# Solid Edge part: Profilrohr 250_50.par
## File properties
Username: ahadarics
Dokumentum tartalom típus: 0
Author: ahadarics
Last saved by: ahadarics
Revision: 79
Sűrűség: 0,000 kg/m^3
Pontosság: 0,990
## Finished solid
Body 1: solid body, 8 faces, 12 edges, 6 vertices.
  Faces by surface: cone 4, cylinder 2, plane 2
  Edges by curve: circle 8, line 4
Bounding box of the edges (mm): 262.000 x 130.000 x 262.000, from (-131, -77.5, -131) to (131, 52.5, 131).
Cylindrical faces by radius (mm): R125 x1, R131 x1
Conical faces (half-angle, radius in mm at the cone's reference point): 45 deg R125.25 x2, 45 deg R130.9 x2
Planar faces by outward normal: +y 1, -y 1
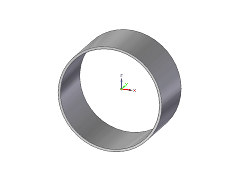
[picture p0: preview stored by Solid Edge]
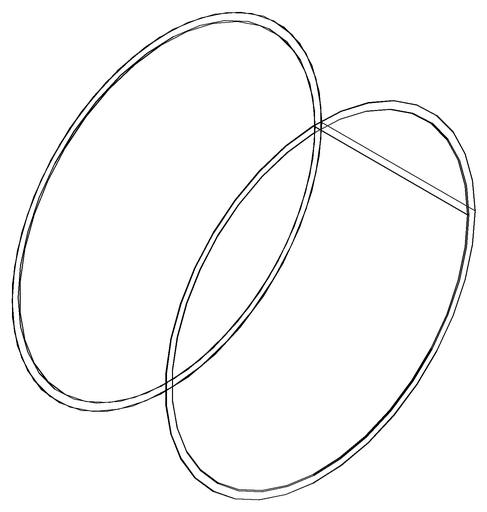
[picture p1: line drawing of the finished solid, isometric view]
